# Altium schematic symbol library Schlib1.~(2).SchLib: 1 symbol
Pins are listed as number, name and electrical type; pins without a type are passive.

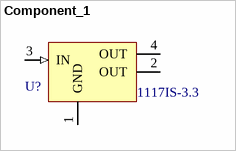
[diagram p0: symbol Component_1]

## Component_1
designator U?, comment 1117IS-3.3
pins: 1 GND, 2 OUT, 3 IN (in), 4 OUT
